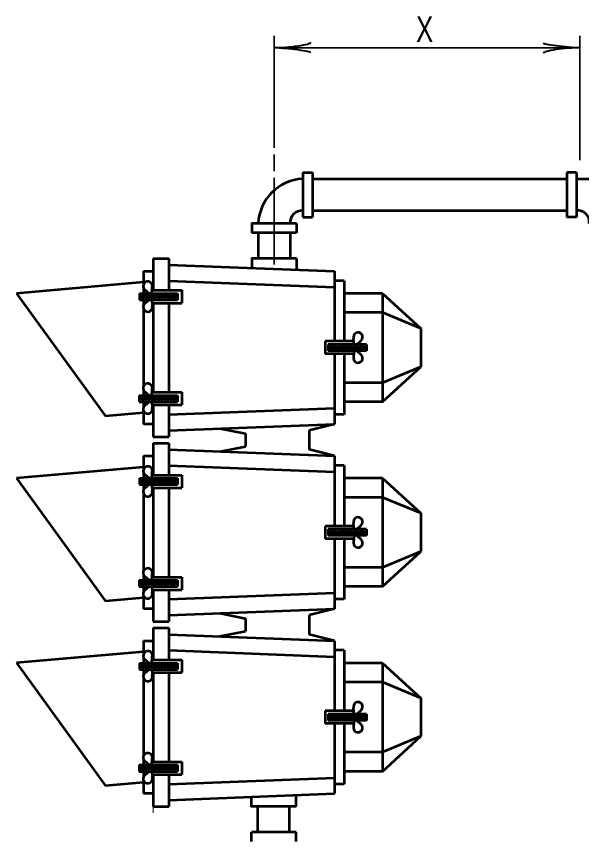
# Model space of a CAD drawing. Extents: x -286 to 394, y -156 to 284.
# Drawn here: x 111.1 to 155.4, y 18.6 to 83.3 of the extents above; entities that cross this region are included whole.
import ezdxf
from ezdxf.enums import TextEntityAlignment as Align

# ---------------------------------------------------------------- set-up
doc = ezdxf.new("R2010")
doc.units = 0
doc.header["$LTSCALE"] = 0.8
doc.layers.add('1', color=7, linetype='Continuous', lineweight=53)

msp = doc.modelspace()

# ---------------------------------------------------------------- linework, layer by layer
at = {"layer": '1', "lineweight": 35}
for p, q in [((131.3158, 81.8035), (131.3158, 73.0153)), ((155.3158, 81.8035), (155.3158, 72.0458)), ((131.3158, 80.8652), (155.3158, 80.8652)), ((131.3158, 72.4785), (131.3158, 71.17)), ((131.3158, 70.6667), (131.3158, 63.856))]:
    msp.add_line(p, q, dxfattribs=at)
at = {"layer": '1'}
for p, q in [((133.5658, 71.0858), (133.5658, 67.5858)), ((133.5658, 71.0858), (134.3158, 71.0858)), ((134.3158, 71.0858), (134.3158, 67.5858)), ((134.3158, 70.5858), (154.2946, 70.5858)), ((154.2946, 71.0858), (154.2946, 67.5858)), ((155.0446, 71.0858), (154.2946, 71.0858)), ((155.0446, 71.0858), (155.0446, 67.5858)), ((155.0446, 70.5858), (159.3342, 70.5858)), ((134.3158, 68.0858), (154.2946, 68.0858)), ((133.5658, 67.5858), (134.3158, 67.5858)), ((155.0446, 67.5858), (154.2946, 67.5858)), ((133.0658, 67.0858), (133.0658, 66.3358)), ((133.0658, 66.3358), (129.5658, 66.3358)), ((130.0658, 66.3358), (130.0658, 64.3358)), ((132.5658, 66.3358), (132.5658, 64.3358)), ((121.8157, 64.3358), (123.0657, 64.3358)), ((121.8157, 64.3358), (121.8157, 61.8358)), ((123.0657, 64.3358), (123.0657, 61.8358)), ((131.3158, 64.3358), (131.3158, 64.3242)), ((133.0658, 64.3358), (133.0658, 63.4512)), ((123.0657, 63.8358), (136.0658, 63.3358)), ((121.0657, 63.3358), (121.8157, 63.3358)), ((121.0657, 63.3358), (121.0657, 62.2799)), ((136.0658, 63.3358), (136.0658, 57.8358)), ((121.0657, 62.4608), (111.1038, 61.5892)), ((123.0657, 62.585), (136.0658, 62.085)), ((136.8158, 62.5858), (136.0658, 62.5858)), ((136.8158, 62.5858), (136.8158, 57.8358)), ((111.1038, 61.5892), (118.0772, 51.9493)), ((120.743, 61.5868), (120.743, 61.0868)), ((120.743, 61.5868), (123.743, 61.5868)), ((120.993, 61.5868), (120.993, 61.0868)), ((121.0657, 62.0381), (121.0657, 61.5868)), ((121.5082, 61.5868), (121.1522, 61.901)), ((121.243, 61.5868), (121.243, 61.0868)), ((121.493, 61.5868), (121.493, 61.0868)), ((121.7156, 61.5868), (121.7537, 62.0397)), ((121.743, 61.5868), (121.743, 61.0868)), ((121.8157, 61.8358), (124.0657, 61.8358)), ((121.993, 61.5868), (121.993, 61.0868)), ((122.243, 61.5868), (122.243, 61.0868)), ((122.493, 61.5868), (122.493, 61.0868)), ((122.743, 61.5868), (122.743, 61.0868)), ((122.993, 61.5868), (122.993, 61.0868)), ((123.243, 61.5868), (123.243, 61.0868)), ((123.493, 61.5868), (123.493, 61.0868)), ((123.743, 61.5868), (123.743, 61.0868)), ((124.0657, 61.8358), (124.0657, 60.8358)), ((139.8158, 61.5858), (136.8158, 61.5858)), ((139.8158, 61.5858), (139.8158, 53.0858)), ((139.8158, 61.5858), (142.8158, 58.8358)), ((120.743, 61.0868), (123.743, 61.0868)), ((120.868, 61.4618), (120.868, 61.2118)), ((121.0657, 61.0868), (121.0657, 60.6367)), ((121.118, 61.4618), (121.118, 61.2118)), ((121.5082, 61.088), (121.1522, 60.7738)), ((121.368, 61.4618), (121.368, 61.2118)), ((121.618, 61.4618), (121.618, 61.2118)), ((121.7156, 61.088), (121.7537, 60.6351)), ((121.868, 61.4618), (121.868, 61.2118)), ((122.118, 61.4618), (122.118, 61.2118)), ((122.368, 61.4618), (122.368, 61.2118)), ((122.618, 61.4618), (122.618, 61.2118)), ((122.868, 61.4618), (122.868, 61.2118)), ((123.118, 61.4618), (123.118, 61.2118)), ((123.368, 61.4618), (123.368, 61.2118)), ((123.618, 61.4618), (123.618, 61.2118)), ((121.0657, 60.3949), (121.0657, 54.2952)), ((121.8157, 60.8358), (124.0657, 60.8358)), ((121.8157, 60.8358), (121.8157, 53.8358)), ((123.0657, 60.8358), (123.0657, 53.8358)), ((139.8158, 60.0858), (136.8158, 60.0858)), ((142.8158, 58.8358), (139.8158, 60.0858)), ((142.8158, 58.8358), (142.8158, 55.8358)), ((137.5721, 57.8358), (135.3158, 57.8358)), ((135.3158, 57.8358), (135.3158, 56.8358)), ((137.5932, 57.5858), (137.555, 58.0388)), ((137.8006, 57.5858), (138.1565, 57.9)), ((138.5658, 57.5858), (135.5658, 57.5858)), ((135.5658, 57.5858), (135.5658, 57.0858)), ((138.5658, 57.0858), (135.5658, 57.0858)), ((135.6908, 57.4608), (135.6908, 57.2108)), ((135.8158, 57.5858), (135.8158, 57.0858)), ((135.9408, 57.4608), (135.9408, 57.2108)), ((136.0658, 57.5858), (136.0658, 57.0858)), ((136.1908, 57.4608), (136.1908, 57.2108)), ((136.3158, 57.5858), (136.3158, 57.0858)), ((136.4408, 57.4608), (136.4408, 57.2108)), ((136.5658, 57.5858), (136.5658, 57.0858)), ((136.5658, 57.4608), (136.5658, 57.2108)), ((136.6908, 57.4608), (136.6908, 57.2108)), ((136.8158, 57.5858), (136.8158, 57.0858)), ((136.9408, 57.4608), (136.9408, 57.2108)), ((137.0658, 57.5858), (137.0658, 57.0858)), ((137.1908, 57.4608), (137.1908, 57.2108)), ((137.3158, 57.5858), (137.3158, 57.0858)), ((137.4408, 57.4608), (137.4408, 57.2108)), ((137.5932, 57.087), (137.555, 56.6341)), ((137.5658, 57.5858), (137.5658, 57.0858)), ((137.6908, 57.4608), (137.6908, 57.2108)), ((137.8006, 57.087), (138.1565, 56.7728)), ((137.8158, 57.5858), (137.8158, 57.0858)), ((137.9408, 57.4608), (137.9408, 57.2108)), ((138.0658, 57.5858), (138.0658, 57.0858)), ((138.1908, 57.4608), (138.1908, 57.2108)), ((138.3158, 57.5858), (138.3158, 57.0858)), ((138.4408, 57.4608), (138.4408, 57.2108)), ((138.5658, 57.5858), (138.5658, 57.0858)), ((137.5658, 56.8358), (135.3158, 56.8358)), ((136.0658, 56.8358), (136.0658, 51.3358)), ((136.8158, 56.8358), (136.8158, 52.0858)), ((139.8158, 53.0858), (142.8158, 55.8358)), ((142.8158, 55.8358), (139.8158, 54.5858)), ((139.8158, 54.5858), (136.8158, 54.5858)), ((121.0657, 54.0201), (121.0657, 53.5855)), ((121.5018, 53.5855), (121.1459, 53.8997)), ((121.7092, 53.5855), (121.7474, 54.0384)), ((121.8157, 53.8358), (124.0657, 53.8358)), ((124.0657, 53.8358), (124.0657, 52.8358)), ((120.7367, 53.5855), (120.7367, 53.0855)), ((120.7367, 53.5855), (123.7367, 53.5855)), ((120.7367, 53.0855), (123.7367, 53.0855)), ((120.8617, 53.4605), (120.8617, 53.2105)), ((120.9867, 53.5855), (120.9867, 53.0855)), ((121.0657, 53.0855), (121.0657, 52.6521)), ((121.1117, 53.4605), (121.1117, 53.2105)), ((121.5018, 53.0867), (121.1459, 52.7725)), ((121.2367, 53.5855), (121.2367, 53.0855)), ((121.3617, 53.4605), (121.3617, 53.2105)), ((121.4867, 53.5855), (121.4867, 53.0855)), ((121.6117, 53.4605), (121.6117, 53.2105)), ((121.7092, 53.0867), (121.7474, 52.6337)), ((121.7367, 53.5855), (121.7367, 53.0855)), ((121.8617, 53.4605), (121.8617, 53.2105)), ((121.9867, 53.5855), (121.9867, 53.0855)), ((122.1117, 53.4605), (122.1117, 53.2105)), ((122.2367, 53.5855), (122.2367, 53.0855)), ((122.3617, 53.4605), (122.3617, 53.2105)), ((122.4867, 53.5855), (122.4867, 53.0855)), ((122.6117, 53.4605), (122.6117, 53.2105)), ((122.7367, 53.5855), (122.7367, 53.0855)), ((122.8617, 53.4605), (122.8617, 53.2105)), ((122.9867, 53.5855), (122.9867, 53.0855)), ((123.1117, 53.4605), (123.1117, 53.2105)), ((123.2367, 53.5855), (123.2367, 53.0855)), ((123.3617, 53.4605), (123.3617, 53.2105)), ((123.4867, 53.5855), (123.4867, 53.0855)), ((123.6117, 53.4605), (123.6117, 53.2105)), ((123.7367, 53.5855), (123.7367, 53.0855)), ((139.8158, 53.0858), (136.8158, 53.0858)), ((121.8157, 52.8358), (124.0657, 52.8358)), ((121.8157, 52.8358), (121.8157, 50.3358)), ((123.0657, 52.8358), (123.0657, 50.3358)), ((123.0657, 52.0867), (136.0658, 52.5867)), ((121.0657, 52.2108), (118.0772, 51.9493)), ((121.0657, 52.3769), (121.0657, 51.3358)), ((136.8158, 52.0858), (136.0658, 52.0858)), ((121.8157, 51.3358), (121.0657, 51.3358)), ((123.0657, 50.8358), (136.0658, 51.3358)), ((136.0658, 51.3358), (134.0648, 50.8358)), ((127.0627, 50.9896), (129.0648, 50.5858)), ((129.0648, 50.5858), (129.0648, 49.5858)), ((134.0648, 50.8358), (134.0648, 49.3358)), ((121.8157, 50.3358), (123.0657, 50.3358)), ((121.8157, 49.8358), (123.0657, 49.8358)), ((121.8157, 49.8358), (121.8157, 47.3358)), ((123.0657, 49.8358), (123.0657, 47.3358)), ((123.0657, 49.3359), (136.0658, 48.8358)), ((127.0627, 49.1822), (129.0648, 49.5858)), ((136.0658, 48.8358), (134.0648, 49.3358)), ((121.0657, 48.8358), (121.8157, 48.8358)), ((121.0657, 48.8358), (121.0657, 47.7799)), ((136.0658, 48.8358), (136.0658, 43.3358)), ((121.0657, 47.9608), (111.1038, 47.0892)), ((123.0657, 48.085), (136.0658, 47.585)), ((136.8158, 48.0858), (136.0658, 48.0858)), ((136.8158, 48.0858), (136.8158, 43.3358)), ((121.0657, 47.5381), (121.0657, 47.0868)), ((121.5082, 47.0868), (121.1522, 47.401)), ((121.7156, 47.0868), (121.7537, 47.5397)), ((121.8157, 47.3358), (124.0657, 47.3358)), ((124.0657, 47.3358), (124.0657, 46.3358)), ((111.1038, 47.0892), (118.0772, 37.4493)), ((120.743, 47.0868), (120.743, 46.5868)), ((120.743, 47.0868), (123.743, 47.0868)), ((120.868, 46.9618), (120.868, 46.7118)), ((120.993, 47.0868), (120.993, 46.5868)), ((121.118, 46.9618), (121.118, 46.7118)), ((121.243, 47.0868), (121.243, 46.5868)), ((121.368, 46.9618), (121.368, 46.7118)), ((121.493, 47.0868), (121.493, 46.5868)), ((121.618, 46.9618), (121.618, 46.7118)), ((121.743, 47.0868), (121.743, 46.5868)), ((121.868, 46.9618), (121.868, 46.7118)), ((121.993, 47.0868), (121.993, 46.5868)), ((122.118, 46.9618), (122.118, 46.7118)), ((122.243, 47.0868), (122.243, 46.5868)), ((122.368, 46.9618), (122.368, 46.7118)), ((122.493, 47.0868), (122.493, 46.5868)), ((122.618, 46.9618), (122.618, 46.7118)), ((122.743, 47.0868), (122.743, 46.5868)), ((122.868, 46.9618), (122.868, 46.7118)), ((122.993, 47.0868), (122.993, 46.5868)), ((123.118, 46.9618), (123.118, 46.7118)), ((123.243, 47.0868), (123.243, 46.5868)), ((123.368, 46.9618), (123.368, 46.7118)), ((123.493, 47.0868), (123.493, 46.5868)), ((123.618, 46.9618), (123.618, 46.7118)), ((123.743, 47.0868), (123.743, 46.5868)), ((139.8158, 47.0858), (136.8158, 47.0858)), ((139.8158, 47.0858), (139.8158, 38.5858)), ((139.8158, 47.0858), (142.8158, 44.3358)), ((120.743, 46.5868), (123.743, 46.5868)), ((121.0657, 46.5868), (121.0657, 46.1367)), ((121.5082, 46.588), (121.1522, 46.2738)), ((121.7156, 46.588), (121.7537, 46.1351)), ((121.8157, 46.3358), (124.0657, 46.3358)), ((121.8157, 46.3358), (121.8157, 39.3358)), ((123.0657, 46.3358), (123.0657, 39.3358)), ((121.0657, 45.8949), (121.0657, 39.7952)), ((139.8158, 45.5858), (136.8158, 45.5858)), ((142.8158, 44.3358), (139.8158, 45.5858)), ((142.8158, 44.3358), (142.8158, 41.3358)), ((137.5932, 43.0858), (137.555, 43.5388)), ((137.8006, 43.0858), (138.1565, 43.4)), ((137.5721, 43.3358), (135.3158, 43.3358)), ((135.3158, 43.3358), (135.3158, 42.3358)), ((138.5658, 43.0858), (135.5658, 43.0858)), ((135.5658, 43.0858), (135.5658, 42.5858)), ((135.6908, 42.9608), (135.6908, 42.7108)), ((135.8158, 43.0858), (135.8158, 42.5858)), ((135.9408, 42.9608), (135.9408, 42.7108)), ((136.0658, 43.0858), (136.0658, 42.5858)), ((136.1908, 42.9608), (136.1908, 42.7108)), ((136.3158, 43.0858), (136.3158, 42.5858)), ((136.4408, 42.9608), (136.4408, 42.7108)), ((136.5658, 43.0858), (136.5658, 42.5858)), ((136.5658, 42.9608), (136.5658, 42.7108)), ((136.6908, 42.9608), (136.6908, 42.7108)), ((136.8158, 43.0858), (136.8158, 42.5858)), ((136.9408, 42.9608), (136.9408, 42.7108)), ((137.0658, 43.0858), (137.0658, 42.5858)), ((137.1908, 42.9608), (137.1908, 42.7108)), ((137.3158, 43.0858), (137.3158, 42.5858)), ((137.4408, 42.9608), (137.4408, 42.7108)), ((137.5658, 43.0858), (137.5658, 42.5858)), ((137.6908, 42.9608), (137.6908, 42.7108)), ((137.8158, 43.0858), (137.8158, 42.5858)), ((137.9408, 42.9608), (137.9408, 42.7108)), ((138.0658, 43.0858), (138.0658, 42.5858)), ((138.1908, 42.9608), (138.1908, 42.7108)), ((138.3158, 43.0858), (138.3158, 42.5858)), ((138.4408, 42.9608), (138.4408, 42.7108)), ((138.5658, 43.0858), (138.5658, 42.5858)), ((137.5658, 42.3358), (135.3158, 42.3358)), ((138.5658, 42.5858), (135.5658, 42.5858)), ((136.0658, 42.3358), (136.0658, 36.8358)), ((136.8158, 42.3358), (136.8158, 37.5858)), ((137.5932, 42.587), (137.555, 42.1341)), ((137.8006, 42.587), (138.1565, 42.2728)), ((139.8158, 38.5858), (142.8158, 41.3358)), ((142.8158, 41.3358), (139.8158, 40.0858)), ((121.0657, 39.5201), (121.0657, 39.0855)), ((121.7092, 39.0855), (121.7474, 39.5384)), ((139.8158, 40.0858), (136.8158, 40.0858)), ((120.7367, 39.0855), (120.7367, 38.5855)), ((120.7367, 39.0855), (123.7367, 39.0855)), ((120.8617, 38.9605), (120.8617, 38.7105)), ((120.9867, 39.0855), (120.9867, 38.5855)), ((121.1117, 38.9605), (121.1117, 38.7105)), ((121.5018, 39.0855), (121.1459, 39.3997)), ((121.2367, 39.0855), (121.2367, 38.5855)), ((121.3617, 38.9605), (121.3617, 38.7105)), ((121.4867, 39.0855), (121.4867, 38.5855)), ((121.6117, 38.9605), (121.6117, 38.7105)), ((121.7367, 39.0855), (121.7367, 38.5855)), ((121.8157, 39.3358), (124.0657, 39.3358)), ((121.8617, 38.9605), (121.8617, 38.7105)), ((121.9867, 39.0855), (121.9867, 38.5855)), ((122.1117, 38.9605), (122.1117, 38.7105)), ((122.2367, 39.0855), (122.2367, 38.5855)), ((122.3617, 38.9605), (122.3617, 38.7105)), ((122.4867, 39.0855), (122.4867, 38.5855)), ((122.6117, 38.9605), (122.6117, 38.7105)), ((122.7367, 39.0855), (122.7367, 38.5855)), ((122.8617, 38.9605), (122.8617, 38.7105)), ((122.9867, 39.0855), (122.9867, 38.5855)), ((123.1117, 38.9605), (123.1117, 38.7105)), ((123.2367, 39.0855), (123.2367, 38.5855)), ((123.3617, 38.9605), (123.3617, 38.7105)), ((123.4867, 39.0855), (123.4867, 38.5855)), ((123.6117, 38.9605), (123.6117, 38.7105)), ((123.7367, 39.0855), (123.7367, 38.5855)), ((124.0657, 39.3358), (124.0657, 38.3358)), ((120.7367, 38.5855), (123.7367, 38.5855)), ((121.0657, 38.5855), (121.0657, 38.1521)), ((121.5018, 38.5867), (121.1459, 38.2725)), ((121.7092, 38.5867), (121.7474, 38.1337)), ((121.8157, 38.3358), (124.0657, 38.3358)), ((121.8157, 38.3358), (121.8157, 35.8358)), ((123.0657, 38.3358), (123.0657, 35.8358)), ((139.8158, 38.5858), (136.8158, 38.5858)), ((121.0657, 37.7108), (118.0772, 37.4493)), ((121.0657, 37.8769), (121.0657, 36.8358)), ((123.0657, 37.5868), (136.0658, 38.0868)), ((136.8158, 37.5858), (136.0658, 37.5858)), ((121.8157, 36.8358), (121.0657, 36.8358)), ((123.0657, 36.3358), (136.0658, 36.8358)), ((127.0627, 36.4896), (129.0648, 36.0858)), ((136.0658, 36.8358), (134.0648, 36.3358)), ((134.0648, 36.3358), (134.0648, 34.8358)), ((121.8157, 35.8358), (123.0657, 35.8358)), ((129.0648, 36.0858), (129.0648, 35.0858)), ((121.8157, 35.3358), (123.0657, 35.3358)), ((121.8157, 35.3358), (121.8157, 32.8358)), ((123.0657, 35.3358), (123.0657, 32.8358)), ((127.0627, 34.6822), (129.0648, 35.0858)), ((121.0657, 34.3358), (121.8157, 34.3358)), ((121.0657, 34.3358), (121.0657, 33.2799)), ((123.0657, 34.8358), (136.0658, 34.3358)), ((136.0658, 34.3358), (134.0648, 34.8358)), ((136.0658, 34.3358), (136.0658, 28.8358)), ((121.0657, 33.4608), (111.1038, 32.5892)), ((121.0657, 33.0381), (121.0657, 32.5868)), ((121.7156, 32.5868), (121.7537, 33.0397)), ((123.0657, 33.585), (136.0658, 33.085)), ((136.8158, 33.5858), (136.0658, 33.5858)), ((136.8158, 33.5858), (136.8158, 28.8358)), ((111.1038, 32.5892), (118.0772, 22.9493)), ((120.743, 32.5868), (120.743, 32.0868)), ((120.743, 32.5868), (123.743, 32.5868)), ((120.868, 32.4618), (120.868, 32.2118)), ((120.993, 32.5868), (120.993, 32.0868)), ((121.118, 32.4618), (121.118, 32.2118)), ((121.5082, 32.5868), (121.1522, 32.901)), ((121.243, 32.5868), (121.243, 32.0868)), ((121.368, 32.4618), (121.368, 32.2118)), ((121.493, 32.5868), (121.493, 32.0868)), ((121.618, 32.4618), (121.618, 32.2118)), ((121.743, 32.5868), (121.743, 32.0868)), ((121.8157, 32.8358), (124.0657, 32.8358)), ((121.868, 32.4618), (121.868, 32.2118)), ((121.993, 32.5868), (121.993, 32.0868)), ((122.118, 32.4618), (122.118, 32.2118)), ((122.243, 32.5868), (122.243, 32.0868)), ((122.368, 32.4618), (122.368, 32.2118)), ((122.493, 32.5868), (122.493, 32.0868)), ((122.618, 32.4618), (122.618, 32.2118)), ((122.743, 32.5868), (122.743, 32.0868)), ((122.868, 32.4618), (122.868, 32.2118)), ((122.993, 32.5868), (122.993, 32.0868)), ((123.118, 32.4618), (123.118, 32.2118)), ((123.243, 32.5868), (123.243, 32.0868)), ((123.368, 32.4618), (123.368, 32.2118)), ((123.493, 32.5868), (123.493, 32.0868)), ((123.618, 32.4618), (123.618, 32.2118)), ((123.743, 32.5868), (123.743, 32.0868)), ((124.0657, 32.8358), (124.0657, 31.8358)), ((139.8158, 32.5858), (136.8158, 32.5858)), ((139.8158, 32.5858), (139.8158, 24.0858)), ((139.8158, 32.5858), (142.8158, 29.8358)), ((120.743, 32.0868), (123.743, 32.0868)), ((121.0657, 32.0868), (121.0657, 31.6367)), ((121.5082, 32.088), (121.1522, 31.7738)), ((121.7156, 32.088), (121.7537, 31.6351)), ((121.8157, 31.8358), (124.0657, 31.8358)), ((121.8157, 31.8358), (121.8157, 24.8358)), ((123.0657, 31.8358), (123.0657, 24.8358)), ((121.0657, 31.3949), (121.0657, 25.2952)), ((139.8158, 31.0858), (136.8158, 31.0858)), ((142.8158, 29.8358), (139.8158, 31.0858)), ((142.8158, 29.8358), (142.8158, 26.8358)), ((137.5721, 28.8358), (135.3158, 28.8358)), ((135.3158, 28.8358), (135.3158, 27.8358)), ((138.5658, 28.5858), (135.5658, 28.5858)), ((135.5658, 28.5858), (135.5658, 28.0858)), ((135.8158, 28.5858), (135.8158, 28.0858)), ((136.0658, 28.5858), (136.0658, 28.0858)), ((136.3158, 28.5858), (136.3158, 28.0858)), ((136.5658, 28.5858), (136.5658, 28.0858)), ((136.8158, 28.5858), (136.8158, 28.0858)), ((137.0658, 28.5858), (137.0658, 28.0858)), ((137.3158, 28.5858), (137.3158, 28.0858)), ((137.5932, 28.5858), (137.555, 29.0388)), ((137.5658, 28.5858), (137.5658, 28.0858)), ((137.8006, 28.5858), (138.1565, 28.9)), ((137.8158, 28.5858), (137.8158, 28.0858)), ((138.0658, 28.5858), (138.0658, 28.0858)), ((138.3158, 28.5858), (138.3158, 28.0858)), ((138.5658, 28.5858), (138.5658, 28.0858)), ((138.5658, 28.0858), (135.5658, 28.0858)), ((135.6908, 28.4608), (135.6908, 28.2108)), ((135.9408, 28.4608), (135.9408, 28.2108)), ((136.1908, 28.4608), (136.1908, 28.2108)), ((136.4408, 28.4608), (136.4408, 28.2108)), ((136.5658, 28.4608), (136.5658, 28.2108)), ((136.6908, 28.4608), (136.6908, 28.2108)), ((136.9408, 28.4608), (136.9408, 28.2108)), ((137.1908, 28.4608), (137.1908, 28.2108)), ((137.4408, 28.4608), (137.4408, 28.2108)), ((137.5932, 28.087), (137.555, 27.6341)), ((137.6908, 28.4608), (137.6908, 28.2108)), ((137.8006, 28.087), (138.1565, 27.7728)), ((137.9408, 28.4608), (137.9408, 28.2108)), ((138.1908, 28.4608), (138.1908, 28.2108)), ((138.4408, 28.4608), (138.4408, 28.2108)), ((137.5658, 27.8358), (135.3158, 27.8358)), ((136.0658, 27.8358), (136.0658, 22.3358)), ((136.8158, 27.8358), (136.8158, 23.0858)), ((139.8158, 24.0858), (142.8158, 26.8358)), ((142.8158, 26.8358), (139.8158, 25.5858)), ((139.8158, 25.5858), (136.8158, 25.5858)), ((121.0657, 25.0201), (121.0657, 24.5855)), ((121.5018, 24.5855), (121.1459, 24.8997)), ((121.7092, 24.5855), (121.7474, 25.0384)), ((121.8157, 24.8358), (124.0657, 24.8358)), ((124.0657, 24.8358), (124.0657, 23.8358)), ((120.7367, 24.5855), (120.7367, 24.0855)), ((120.7367, 24.5855), (123.7367, 24.5855)), ((120.7367, 24.0855), (123.7367, 24.0855)), ((120.8617, 24.4605), (120.8617, 24.2105)), ((120.9867, 24.5855), (120.9867, 24.0855)), ((121.0657, 24.0855), (121.0657, 23.6521)), ((121.1117, 24.4605), (121.1117, 24.2105)), ((121.5018, 24.0867), (121.1459, 23.7725)), ((121.2367, 24.5855), (121.2367, 24.0855)), ((121.3617, 24.4605), (121.3617, 24.2105)), ((121.4867, 24.5855), (121.4867, 24.0855)), ((121.6117, 24.4605), (121.6117, 24.2105)), ((121.7092, 24.0867), (121.7474, 23.6337)), ((121.7367, 24.5855), (121.7367, 24.0855)), ((121.8617, 24.4605), (121.8617, 24.2105)), ((121.9867, 24.5855), (121.9867, 24.0855)), ((122.1117, 24.4605), (122.1117, 24.2105)), ((122.2367, 24.5855), (122.2367, 24.0855)), ((122.3617, 24.4605), (122.3617, 24.2105)), ((122.4867, 24.5855), (122.4867, 24.0855)), ((122.6117, 24.4605), (122.6117, 24.2105)), ((122.7367, 24.5855), (122.7367, 24.0855)), ((122.8617, 24.4605), (122.8617, 24.2105)), ((122.9867, 24.5855), (122.9867, 24.0855)), ((123.1117, 24.4605), (123.1117, 24.2105)), ((123.2367, 24.5855), (123.2367, 24.0855)), ((123.3617, 24.4605), (123.3617, 24.2105)), ((123.4867, 24.5855), (123.4867, 24.0855)), ((123.6117, 24.4605), (123.6117, 24.2105)), ((123.7367, 24.5855), (123.7367, 24.0855)), ((139.8158, 24.0858), (136.8158, 24.0858)), ((121.0657, 23.3769), (121.0657, 22.3358)), ((121.8157, 23.8358), (124.0657, 23.8358)), ((121.8157, 23.8358), (121.8157, 21.3358)), ((123.0657, 23.8358), (123.0657, 21.3358)), ((123.0657, 23.0867), (136.0658, 23.5867)), ((121.0657, 23.2108), (118.0772, 22.9493)), ((136.8158, 23.0858), (136.0658, 23.0858)), ((121.8157, 22.3358), (121.0657, 22.3358)), ((123.0657, 21.8358), (136.0658, 22.3358)), ((133.0362, 21.3247), (133.0362, 22.2093)), ((121.8157, 21.3358), (123.0657, 21.3358)), ((130.0362, 19.3247), (130.0362, 21.3247)), ((132.5362, 19.3247), (132.5362, 21.3247)), ((133.0362, 19.3247), (129.5362, 19.3247)), ((129.5362, 18.5747), (129.5362, 19.3247)), ((133.0362, 18.5747), (133.0362, 19.3247))]:
    msp.add_line(p, q, dxfattribs=at)
at = {"layer": '1', "lineweight": 13}
msp.add_line((121.8157, 21.3358), (121.8157, 20.8358), dxfattribs=at)
at = {"layer": '1'}
for points in [[(133.0658, 67.0858), (129.5658, 67.0858), (129.5658, 66.3358)], [(133.0658, 64.3358), (129.5658, 64.3358), (129.5658, 63.5858)], [(133.0362, 21.3247), (129.5362, 21.3247), (129.5362, 22.0747)]]:
    msp.add_lwpolyline(points, dxfattribs=at)
for centre, radius, start, end in [((133.7521, 66.8995), 3.6911, 92.89399, 177.10601), ((133.4981, 67.1535), 0.9348, 85.85174, 184.14826), ((155.1436, 67.1848), 0.9064, 353.73087, 96.26912), ((121.4096, 62.159), 0.3644, 340.87038, 225.06771), ((121.4096, 60.5158), 0.3644, 134.93229, 19.12962), ((137.8992, 58.158), 0.3644, 314.93229, 199.12962), ((137.8992, 56.5148), 0.3644, 160.87038, 45.06771), ((121.4032, 54.1577), 0.3644, 340.87038, 225.06771), ((121.4032, 52.5145), 0.3644, 134.93229, 19.12962), ((121.4096, 47.659), 0.3644, 340.87038, 225.06771), ((121.4096, 46.0158), 0.3644, 134.93229, 19.12962), ((137.8992, 43.658), 0.3644, 314.93229, 199.12962), ((137.8992, 42.0148), 0.3644, 160.87038, 45.06771), ((121.4032, 39.6577), 0.3644, 340.87038, 225.06771), ((121.4032, 38.0145), 0.3644, 134.93229, 19.12962), ((121.4096, 33.159), 0.3644, 340.87038, 225.06771), ((121.4096, 31.5158), 0.3644, 134.93229, 19.12962), ((137.8992, 29.158), 0.3644, 314.93229, 199.12962), ((137.8992, 27.5148), 0.3644, 160.87038, 45.06771), ((121.4032, 25.1577), 0.3644, 340.87038, 225.06771), ((121.4032, 23.5145), 0.3644, 134.93229, 19.12962)]:
    msp.add_arc(centre, radius, start, end, dxfattribs=at)
at = {"layer": '1', "lineweight": 40}
for centre, major_axis, ratio, start_param, end_param in [((132.4069, 81.1415), (-1.7857, -0.1562), 0.122415, 0.8963533, 3.1415927), ((132.4069, 81.1415), (-1.7857, -0.1562), 0.122415, 0.8963533, 3.1415927), ((154.1952, 81.0768), (1.7565, -0.1757), 0.07063, 3.1407148, 5.41811), ((154.1952, 81.0768), (1.7565, -0.1757), 0.07063, 3.1407148, 5.41811), ((132.4363, 80.6536), (-1.7565, 0.1757), 0.07063, 3.1407148, 5.41811), ((132.4363, 80.6536), (-1.7565, 0.1757), 0.07063, 3.1407148, 5.41811), ((154.2246, 80.5889), (1.7857, 0.1562), 0.122415, 0.8963533, 3.1415927), ((154.2246, 80.5889), (1.7857, 0.1562), 0.122415, 0.8963533, 3.1415927)]:
    msp.add_ellipse(centre, major_axis=major_axis, ratio=ratio, start_param=start_param, end_param=end_param, dxfattribs=at)

# ---------------------------------------------------------------- texts
at = {"layer": '1', "width": 0.75}
msp.add_text('X', height=2, dxfattribs=at).set_placement((143.1258, 81.3193), align=Align.CENTER)

doc.saveas('drawing.dxf')
